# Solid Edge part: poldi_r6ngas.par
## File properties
Author: Mac
Template: Normal.par
Last saved by: Mac
Revision: 4
Application: Solid Edge
Material: Stainless steel
Face Style: Steel
Fill Style: ANSI32(Steel)
Virtual Style: Stainless steel
Coef. of Thermal Exp: 1.6e-05
Thermal Conductivity: 17.0
Specific Heat: 502.0
Modulus of Elasticity: 193053196000.0
Poission's Ratio: 0.29
Yield Stress: 310264065.0
Ultimate Stress: 641212401.0
Elongation: 0.0
Density: 7750,000 kg/m^3
Accuracy: 0,990
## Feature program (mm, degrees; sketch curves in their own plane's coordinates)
sketch for "unnamed RevolvedProtrusion 1" plane through (0, 0, 0) normal (0, -1, 0) x-axis (1, 0, 0)
  circle centre (0.3, 0) radius 0.0598
revolve "unnamed RevolvedProtrusion 1" add finite
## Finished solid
Body 1: solid body, 3 faces, 2 edges, 0 vertices.
  Faces by surface: plane 2, torus 1
  Edges by curve: circle 2
Bounding box of the edges (mm; curved faces can reach further): 0.120 x 0.006 x 0.120, from (0.2401, 0, -0.0598) to (0.3598, 0.0063, 0.0598).
Toroidal faces (ring radius, tube radius in mm): R0.3 r0.0598 x1
Planar faces by outward normal: +y 1, oblique 1
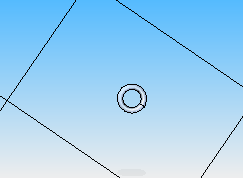
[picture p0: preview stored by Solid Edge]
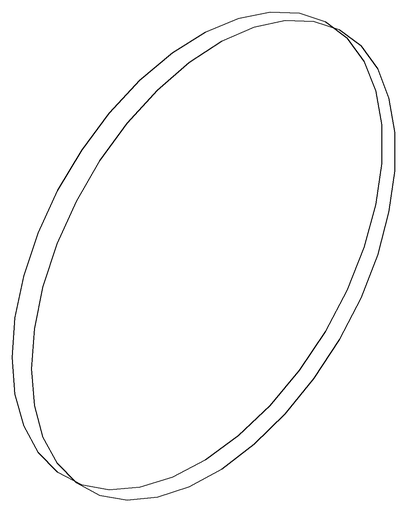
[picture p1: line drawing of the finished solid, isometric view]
